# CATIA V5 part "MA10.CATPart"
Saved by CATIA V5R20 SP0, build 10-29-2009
Part number: MA10
Definition: NONE
Nomenclature: MA10
Source: Unknown
Description: MA10
Bounding box of the stored display mesh (mm): x 0 to 12, y -5 to 5, z -5 to 5
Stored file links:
  C:\Users\Utente\Desktop\IO LAVORO\3D X SITO CF\X SITO\PLASTICA\CFMR\MA10.CATPart
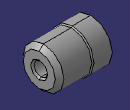
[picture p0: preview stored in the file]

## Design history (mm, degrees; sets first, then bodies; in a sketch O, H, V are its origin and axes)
Body1 "MA10" (main body)
  Solid1: solid without history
